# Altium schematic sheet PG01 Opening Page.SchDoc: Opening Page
size B; Date: 2/10/2009; ApprovedBy: Touraj; DrawnBy: Juan A. Nadal; Engineer: Touraj; Organization: ActiveWave; Address1: 902 Clint Moore Rd., Suite 118; Address2: Boca Raton; Address3: FL, 33487; Address4: 561-999-9422; DocumentNumber: 1; Revision: 18; SheetNumber: 1; SheetTotal: 4; PageSetup: Record=PageOptions|CenterHorizontal=True|CenterVertical=True|PrintScale=0.68|XCorrection=1.00|YCorrection=1.00|PrintKind=0|BorderSize=5000000|LeftOffset=0|BottomOffset=0|Orientation=2|PaperLength=1000|PaperWidth=1000|Scale=100|PaperSource=7|PrintQuality=-4|MediaType=1|DitherType=10|PaperKind=Letter (8.5 x 11 in.)|PrintScaleMode=1; Project: Tag105
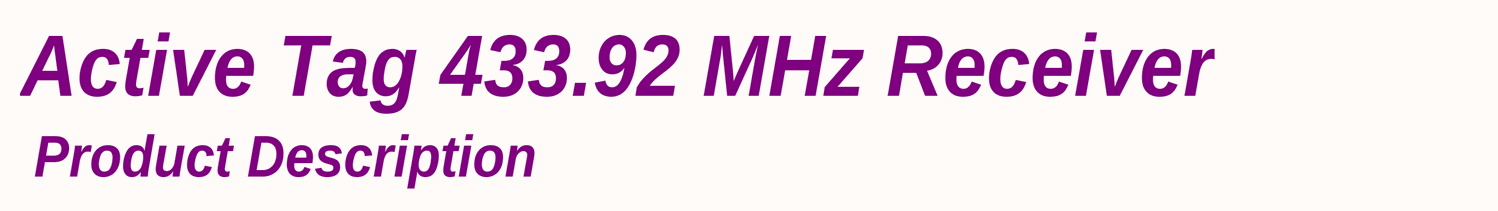
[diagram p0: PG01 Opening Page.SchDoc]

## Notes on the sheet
- Active Tag 433.92 MHz Receiver
- Product Description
